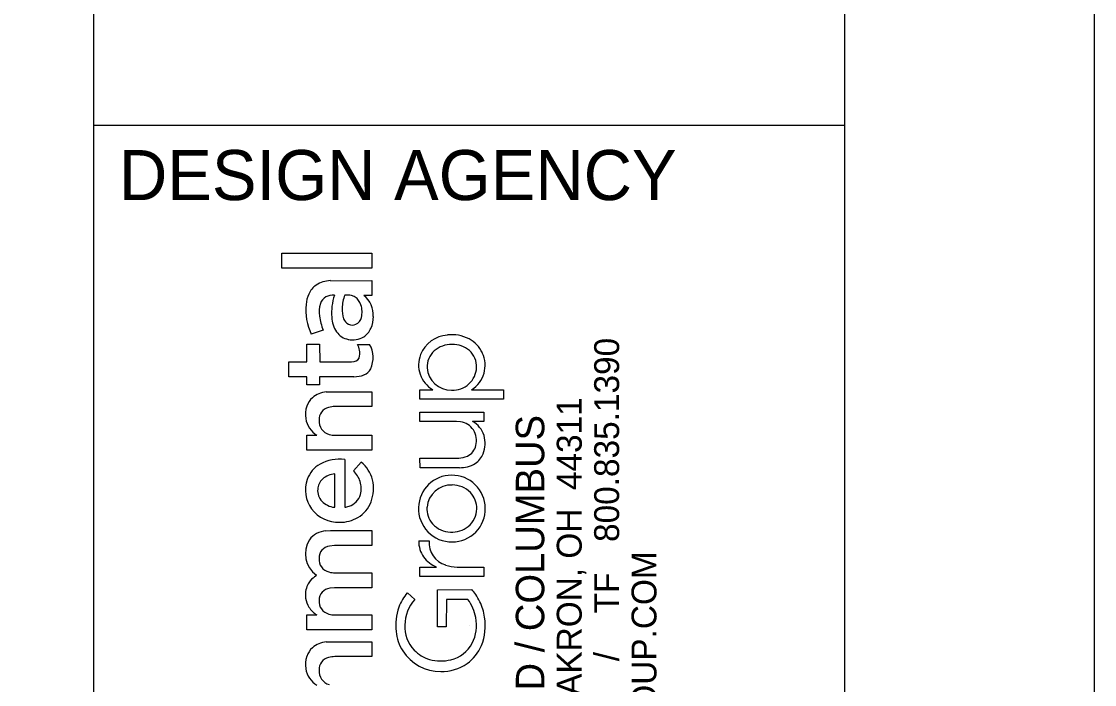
# Model space of a CAD drawing. Extents: x -0.3 to 34, y 0 to 22.
# Drawn here: x 31.855 to 34, y 3.382 to 4.707 of the extents above; entities that cross this region are included whole.
import ezdxf

# ---------------------------------------------------------------- set-up
doc = ezdxf.new("R2010")
doc.units = 0
for name, color, linetype in [('PM_X_CL_Pass_Proh_Lt', 7, 'Continuous'), ('PM_X_Edge_Line', 7, 'Continuous'), ('PM_X_Stop_Line', 7, 'Continuous')]:
    doc.layers.add(name, color=color, linetype=linetype)

msp = doc.modelspace()

# ---------------------------------------------------------------- linework, layer by layer
at = {"layer": 'PM_X_CL_Pass_Proh_Lt'}
msp.add_lwpolyline([(0, 0), (34, 0), (34, 22), (0, 22)], close=True, dxfattribs=at)
at = {"layer": 'PM_X_Edge_Line'}
for p, q in [((32.3756, 4.2141), (32.3756, 4.244)), ((32.3756, 4.244), (32.5557, 4.244)), ((32.5557, 4.244), (32.5557, 4.2141)), ((32.5557, 4.2141), (32.3756, 4.2141)), ((32.4727, 4.189), (32.5555, 4.1892)), ((32.5555, 4.1892), (32.5557, 4.1596)), ((32.5557, 4.1596), (32.5397, 4.1596)), ((32.4582, 4.0904), (32.4343, 4.0823)), ((32.4254, 4.027), (32.4255, 4.0621)), ((32.4255, 4.0621), (32.4511, 4.0621)), ((32.4511, 4.0621), (32.4512, 4.027)), ((32.527, 4.0616), (32.5511, 4.0616)), ((32.3896, 3.9972), (32.3896, 4.027)), ((32.3896, 4.027), (32.4254, 4.027)), ((32.4512, 4.027), (32.515, 4.027)), ((32.515, 4.027), (32.52, 4.0275)), ((32.4254, 3.9972), (32.3896, 3.9972)), ((32.4254, 3.9807), (32.4254, 3.9972)), ((32.5197, 3.9972), (32.4511, 3.9972)), ((32.4511, 3.9972), (32.4511, 3.9807)), ((32.4511, 3.9807), (32.4254, 3.9807)), ((32.6515, 3.9521), (32.6515, 3.9711)), ((32.6515, 3.9711), (32.6771, 3.9711)), ((32.7549, 3.9713), (32.8186, 3.9711)), ((32.8186, 3.9711), (32.8184, 3.9521)), ((32.4644, 3.9669), (32.4729, 3.9673)), ((32.4729, 3.9673), (32.5557, 3.9673)), ((32.5557, 3.9673), (32.5557, 3.9375)), ((32.8184, 3.9521), (32.6515, 3.9521)), ((32.5557, 3.9375), (32.4814, 3.9375)), ((32.6515, 3.908), (32.6515, 3.9267)), ((32.6515, 3.9267), (32.7791, 3.9266)), ((32.7791, 3.9266), (32.7791, 3.908)), ((32.7249, 3.908), (32.6515, 3.908)), ((32.7328, 3.9073), (32.7249, 3.908)), ((32.7791, 3.908), (32.7569, 3.908)), ((32.4254, 3.8503), (32.4254, 3.8802)), ((32.4254, 3.8802), (32.4455, 3.8802)), ((32.4822, 3.8802), (32.5557, 3.8802)), ((32.5557, 3.8802), (32.5557, 3.8504)), ((32.5557, 3.8504), (32.4254, 3.8503)), ((32.5011, 3.8321), (32.5012, 3.7366)), ((32.5188, 3.8093), (32.5342, 3.8266)), ((32.6515, 3.8344), (32.7291, 3.8345)), ((32.6517, 3.8154), (32.6515, 3.8344)), ((32.4814, 3.7364), (32.4814, 3.803)), ((32.7307, 3.8154), (32.6517, 3.8154)), ((32.4802, 3.7363), (32.4814, 3.7364)), ((32.4633, 3.6891), (32.4726, 3.6897)), ((32.4726, 3.6897), (32.5556, 3.6897)), ((32.5556, 3.6897), (32.5557, 3.6598)), ((32.6493, 3.6691), (32.6698, 3.6691)), ((32.4806, 3.6598), (32.471, 3.6588)), ((32.5557, 3.6598), (32.4806, 3.6598)), ((32.4822, 3.6055), (32.5557, 3.6055)), ((32.5557, 3.6055), (32.5557, 3.5757)), ((32.6515, 3.598), (32.6515, 3.617)), ((32.6515, 3.617), (32.6848, 3.617)), ((32.726, 3.617), (32.7791, 3.617)), ((32.7791, 3.617), (32.779, 3.598)), ((32.4444, 3.5992), (32.4446, 3.6007)), ((32.779, 3.598), (32.6515, 3.598)), ((32.4809, 3.5757), (32.4714, 3.5747)), ((32.5557, 3.5757), (32.4809, 3.5757)), ((32.6264, 3.5655), (32.6411, 3.5524)), ((32.6868, 3.5718), (32.7552, 3.5719)), ((32.6868, 3.4978), (32.6868, 3.5718)), ((32.7045, 3.5524), (32.7043, 3.4978)), ((32.7474, 3.5523), (32.7045, 3.5524)), ((32.4254, 3.4915), (32.4254, 3.5214)), ((32.4254, 3.5214), (32.4451, 3.5214)), ((32.4821, 3.5214), (32.5557, 3.5214)), ((32.5557, 3.5214), (32.5557, 3.4916)), ((32.7043, 3.4978), (32.6868, 3.4978)), ((32.75, 3.5), (32.75, 3.5)), ((32.5557, 3.4916), (32.4254, 3.4915)), ((32.4644, 3.4674), (32.4729, 3.4678)), ((32.4729, 3.4678), (32.5557, 3.4678)), ((32.5557, 3.4678), (32.5557, 3.438)), ((32.5557, 3.438), (32.4814, 3.438))]:
    msp.add_line(p, q, dxfattribs=at)
msp.add_lwpolyline([(32.3756, 4.2141), (32.3756, 4.244), (32.5557, 4.244), (32.5557, 4.2141)], close=True, dxfattribs=at)
for points in [[(32.4727, 4.189), (32.5555, 4.1892), (32.5557, 4.1596)], [(32.5557, 4.1596), (32.5397, 4.1596)], [(32.4582, 4.0904), (32.4343, 4.0823)], [(32.5197, 3.9972), (32.4511, 3.9972), (32.4511, 3.9807), (32.4254, 3.9807), (32.4254, 3.9972), (32.3896, 3.9972), (32.3896, 4.027), (32.4254, 4.027), (32.4255, 4.0621), (32.4511, 4.0621), (32.4512, 4.027), (32.515, 4.027), (32.52, 4.0275)], [(32.527, 4.0616), (32.5511, 4.0616)], [(32.7549, 3.9713), (32.8186, 3.9711), (32.8184, 3.9521), (32.6515, 3.9521)], [(32.6515, 3.9521), (32.6515, 3.9711), (32.6771, 3.9711)], [(32.4644, 3.9669), (32.4729, 3.9673), (32.5557, 3.9673), (32.5557, 3.9375), (32.4814, 3.9375)], [(32.7328, 3.9073), (32.7249, 3.908), (32.6515, 3.908), (32.6515, 3.9267), (32.7791, 3.9266), (32.7791, 3.908), (32.7569, 3.908)], [(32.4254, 3.8503), (32.4254, 3.8802), (32.4455, 3.8802)], [(32.4822, 3.8802), (32.5557, 3.8802), (32.5557, 3.8504), (32.4254, 3.8503)], [(32.5011, 3.8321), (32.5012, 3.7366)], [(32.5188, 3.8093), (32.5342, 3.8266)], [(32.7307, 3.8154), (32.6517, 3.8154), (32.6515, 3.8344), (32.7291, 3.8345)], [(32.4802, 3.7363), (32.4814, 3.7364), (32.4814, 3.803)], [(32.4633, 3.6891), (32.4726, 3.6897), (32.5556, 3.6897), (32.5557, 3.6598), (32.4806, 3.6598), (32.471, 3.6588)], [(32.6493, 3.6691), (32.6698, 3.6691)], [(32.4822, 3.6055), (32.5557, 3.6055), (32.5557, 3.5757), (32.4809, 3.5757), (32.4714, 3.5747)], [(32.6515, 3.598), (32.6515, 3.617), (32.6848, 3.617)], [(32.726, 3.617), (32.7791, 3.617), (32.779, 3.598), (32.6515, 3.598)], [(32.4444, 3.5992), (32.4446, 3.6007)], [(32.6264, 3.5655), (32.6411, 3.5524)], [(32.7474, 3.5523), (32.7045, 3.5524), (32.7043, 3.4978), (32.6868, 3.4978), (32.6868, 3.5718), (32.7552, 3.5719)], [(32.4254, 3.4915), (32.4254, 3.5214), (32.4451, 3.5214)], [(32.4821, 3.5214), (32.5557, 3.5214), (32.5557, 3.4916), (32.4254, 3.4915)], [(32.4644, 3.4674), (32.4729, 3.4678), (32.5557, 3.4678), (32.5557, 3.438), (32.4814, 3.438)]]:
    msp.add_lwpolyline(points, dxfattribs=at)
for centre, radius, start, end in [((32.4745, 4.1326), 0.0565, 91.8942, 122.6317), ((32.4745, 4.1326), 0.0565, 91.8942, 122.6317), ((32.4882, 4.1361), 0.0646, 155.9764, 175.3149), ((32.4882, 4.1361), 0.0646, 155.9764, 175.3149), ((32.4685, 4.1447), 0.043, 124.537, 155.6594), ((32.4685, 4.1447), 0.043, 124.537, 155.6594), ((32.5364, 4.1308), 0.113, 174.6101, 205.3899), ((32.5364, 4.1308), 0.113, 174.6101, 205.3899), ((32.5076, 4.1265), 0.0576, 163.1369, 188.1675), ((32.5076, 4.1265), 0.0576, 163.1369, 188.1675), ((32.4753, 4.1356), 0.024, 119.4252, 161.6629), ((32.4753, 4.1356), 0.024, 119.4252, 161.6629), ((32.4779, 4.1278), 0.0321, 85.3802, 116.6222), ((32.4779, 4.1278), 0.0321, 85.3802, 116.6222), ((32.5879, 4.1251), 0.1129, 162.0821, 184.5285), ((32.5879, 4.1251), 0.1129, 162.0821, 184.5285), ((32.5801, 4.1313), 0.0841, 159.8366, 178.0362), ((32.5801, 4.1313), 0.0841, 159.8366, 178.0362), ((32.5051, 4.1074), 0.053, 79.6696, 94.2322), ((32.5051, 4.1074), 0.053, 79.6696, 94.2322), ((32.5089, 4.1364), 0.0238, 56.8913, 76.2149), ((32.5089, 4.1364), 0.0238, 56.8913, 76.2149), ((32.5052, 4.1318), 0.0297, 17.5984, 55.7282), ((32.5052, 4.1318), 0.0297, 17.5984, 55.7282), ((32.4916, 4.1264), 0.0443, 345.9408, 18.9919), ((32.4916, 4.1264), 0.0443, 345.9408, 18.9919), ((32.5055, 4.1191), 0.0529, 358.0746, 49.762), ((32.5055, 4.1191), 0.0529, 358.0746, 49.762), ((32.5466, 4.1303), 0.0506, 175.5903, 199.8857), ((32.5466, 4.1303), 0.0506, 175.5903, 199.8857), ((32.5473, 4.1297), 0.0973, 186.7598, 203.7981), ((32.5473, 4.1297), 0.0973, 186.7598, 203.7981), ((32.5328, 4.1187), 0.0575, 182.5676, 213.7144), ((32.5328, 4.1187), 0.0575, 182.5676, 213.7144), ((32.5164, 4.1189), 0.0184, 198.2844, 293.3081), ((32.5164, 4.1189), 0.0184, 198.2844, 293.3081), ((32.5152, 4.1199), 0.0199, 295.2883, 347.4639), ((32.5152, 4.1199), 0.0199, 295.2883, 347.4639), ((32.5019, 4.1168), 0.0566, 336.016, 0.5951), ((32.5019, 4.1168), 0.0566, 336.016, 0.5951), ((32.5149, 4.1078), 0.0366, 215.0668, 259.8133), ((32.5149, 4.1078), 0.0366, 215.0668, 259.8133), ((32.5175, 4.1131), 0.0423, 257.5256, 300.882), ((32.5175, 4.1131), 0.0423, 257.5256, 300.882), ((32.5175, 4.1097), 0.0394, 303.4436, 336.18), ((32.5175, 4.1097), 0.0394, 303.4436, 336.18), ((32.7108, 4.0182), 0.0624, 93.9866, 158.3119), ((32.7108, 4.0182), 0.0624, 93.9866, 158.3119), ((32.7156, 4.0065), 0.0746, 62.6889, 97.0135), ((32.7156, 4.0065), 0.0746, 62.6889, 97.0135), ((32.4863, 4.042), 0.0452, 10.1545, 25.723), ((32.4863, 4.042), 0.0452, 10.1545, 25.723), ((32.503, 4.0351), 0.0549, 336.589, 28.8991), ((32.503, 4.0351), 0.0549, 336.589, 28.8991), ((32.7138, 4.0102), 0.0513, 87.8965, 131.1812), ((32.7138, 4.0102), 0.0513, 87.8965, 131.1812), ((32.7175, 4.0102), 0.0513, 49.9089, 92.0363), ((32.7175, 4.0102), 0.0513, 49.9089, 92.0363), ((32.7212, 4.0191), 0.0608, 25.0657, 61.9602), ((32.7212, 4.0191), 0.0608, 25.0657, 61.9602), ((32.5184, 4.04), 0.0126, 277.6142, 353.7918), ((32.5184, 4.04), 0.0126, 277.6142, 353.7918), ((32.4957, 4.0436), 0.0356, 351.914, 10.2059), ((32.4957, 4.0436), 0.0356, 351.914, 10.2059), ((32.707, 4.0202), 0.0581, 158.656, 198.171), ((32.707, 4.0202), 0.0581, 158.656, 198.171), ((32.7092, 4.0167), 0.0434, 132.3289, 182.0949), ((32.7092, 4.0167), 0.0434, 132.3289, 182.0949), ((32.7215, 4.0173), 0.0433, 358.0487, 47.9447), ((32.7215, 4.0173), 0.0433, 358.0487, 47.9447), ((32.7245, 4.02), 0.0574, 301.9776, 25.6418), ((32.7245, 4.02), 0.0574, 301.9776, 25.6418), ((32.5291, 4.0261), 0.0275, 292.6889, 332.0598), ((32.5291, 4.0261), 0.0275, 292.6889, 332.0598), ((32.7135, 4.0181), 0.0478, 183.5974, 271.7045), ((32.7135, 4.0181), 0.0478, 183.5974, 271.7045), ((32.7172, 4.018), 0.0477, 267.3149, 357.4019), ((32.7172, 4.018), 0.0477, 267.3149, 357.4019), ((32.5209, 4.0486), 0.0514, 268.6727, 291.5235), ((32.5209, 4.0486), 0.0514, 268.6727, 291.5235), ((32.7103, 4.0243), 0.0627, 200.8399, 238.0162), ((32.7103, 4.0243), 0.0627, 200.8399, 238.0162), ((32.4635, 3.9255), 0.0402, 132.2238, 161.6823), ((32.4635, 3.9255), 0.0402, 132.2238, 161.6823), ((32.4687, 3.9172), 0.0499, 94.9706, 130.2248), ((32.4687, 3.9172), 0.0499, 94.9706, 130.2248), ((32.4787, 3.9211), 0.056, 162.274, 187.7917), ((32.4787, 3.9211), 0.056, 162.274, 187.7917), ((32.4748, 3.9116), 0.025, 103.6868, 182.214), ((32.4748, 3.9116), 0.025, 103.6868, 182.214), ((32.4811, 3.8915), 0.046, 89.6051, 105.3303), ((32.4811, 3.8915), 0.046, 89.6051, 105.3303), ((32.4703, 3.9209), 0.0476, 188.9646, 238.6987), ((32.4703, 3.9209), 0.0476, 188.9646, 238.6987), ((32.4774, 3.9085), 0.0276, 175.5844, 255.1382), ((32.4774, 3.9085), 0.0276, 175.5844, 255.1382), ((32.7271, 3.87), 0.0377, 33.5008, 81.3295), ((32.7271, 3.87), 0.0377, 33.5008, 81.3295), ((32.7324, 3.8648), 0.0496, 17.6221, 60.3897), ((32.7324, 3.8648), 0.0496, 17.6221, 60.3897), ((32.7241, 3.8695), 0.0405, 346.5618, 31.7539), ((32.7241, 3.8695), 0.0405, 346.5618, 31.7539), ((32.4818, 3.9224), 0.0421, 254.0891, 270.5284), ((32.4818, 3.9224), 0.0421, 254.0891, 270.5284), ((32.7234, 3.8641), 0.0584, 339.162, 15.6148), ((32.7234, 3.8641), 0.0584, 339.162, 15.6148), ((32.7337, 3.8662), 0.0304, 294.6321, 348.4863), ((32.7337, 3.8662), 0.0304, 294.6321, 348.4863), ((32.739, 3.859), 0.042, 303.1039, 338.1561), ((32.739, 3.859), 0.042, 303.1039, 338.1561), ((32.4789, 3.7737), 0.0558, 118.8294, 160.6224), ((32.4789, 3.7737), 0.0558, 118.8294, 160.6224), ((32.4918, 3.7487), 0.0839, 83.6212, 118.2845), ((32.4918, 3.7487), 0.0839, 83.6212, 118.2845), ((32.494, 3.7763), 0.0644, 13.5328, 51.3627), ((32.494, 3.7763), 0.0644, 13.5328, 51.3627), ((32.7275, 3.8808), 0.0463, 271.952, 294.0894), ((32.7275, 3.8808), 0.0463, 271.952, 294.0894), ((32.7321, 3.8726), 0.0571, 268.627, 301.4778), ((32.7321, 3.8726), 0.0571, 268.627, 301.4778), ((32.4844, 3.7607), 0.0424, 94.0131, 130.8806), ((32.4844, 3.7607), 0.0424, 94.0131, 130.8806), ((32.4803, 3.7702), 0.0549, 19.0387, 45.4432), ((32.4803, 3.7702), 0.0549, 19.0387, 45.4432), ((32.7143, 3.7348), 0.0655, 89.4821, 178.7775), ((32.7143, 3.7348), 0.0655, 89.4821, 178.7775), ((32.7158, 3.7341), 0.0662, 0.4227, 90.7613), ((32.7158, 3.7341), 0.0662, 0.4227, 90.7613), ((32.487, 3.7707), 0.0644, 160.5214, 215.7815), ((32.487, 3.7707), 0.0644, 160.5214, 215.7815), ((32.477, 3.7709), 0.0298, 132.9855, 177.1802), ((32.477, 3.7709), 0.0298, 132.9855, 177.1802), ((32.4872, 3.7743), 0.047, 344.6072, 17.0067), ((32.4872, 3.7743), 0.047, 344.6072, 17.0067), ((32.4829, 3.7738), 0.0758, 339.3543, 13.3771), ((32.4829, 3.7738), 0.0758, 339.3543, 13.3771), ((32.714, 3.7324), 0.0485, 87.6883, 175.017), ((32.714, 3.7324), 0.0485, 87.6883, 175.017), ((32.7166, 3.7304), 0.0505, 44.912, 90.7591), ((32.7166, 3.7304), 0.0505, 44.912, 90.7591), ((32.4782, 3.7697), 0.0311, 175.0014, 223.2876), ((32.4782, 3.7697), 0.0311, 175.0014, 223.2876), ((32.499, 3.7718), 0.035, 288.0108, 343.5536), ((32.499, 3.7718), 0.035, 288.0108, 343.5536), ((32.7196, 3.7345), 0.0455, 358.3228, 43.8349), ((32.7196, 3.7345), 0.0455, 358.3228, 43.8349), ((32.4891, 3.7752), 0.0687, 217.7434, 271.6561), ((32.4891, 3.7752), 0.0687, 217.7434, 271.6561), ((32.4855, 3.7783), 0.0423, 225.0645, 262.797), ((32.4855, 3.7783), 0.0423, 225.0645, 262.797), ((32.5013, 3.7568), 0.0202, 269.7004, 294.8729), ((32.5013, 3.7568), 0.0202, 269.7004, 294.8729), ((32.4955, 3.7698), 0.0626, 300.9439, 338.7322), ((32.4955, 3.7698), 0.0626, 300.9439, 338.7322), ((32.7148, 3.7334), 0.0661, 177.5373, 270.9452), ((32.7148, 3.7334), 0.0661, 177.5373, 270.9452), ((32.7108, 3.7331), 0.0453, 175.5147, 221.4205), ((32.7108, 3.7331), 0.0453, 175.5147, 221.4205), ((32.7167, 3.7327), 0.0654, 269.3083, 1.6791), ((32.7167, 3.7327), 0.0654, 269.3083, 1.6791), ((32.7193, 3.7337), 0.0457, 308.9038, 359.3095), ((32.7193, 3.7337), 0.0457, 308.9038, 359.3095), ((32.492, 3.777), 0.0706, 269.2053, 300.3357), ((32.492, 3.777), 0.0706, 269.2053, 300.3357), ((32.714, 3.7373), 0.0505, 222.6626, 268.3733), ((32.714, 3.7373), 0.0505, 222.6626, 268.3733), ((32.7157, 3.7386), 0.0518, 266.5531, 308.6725), ((32.7157, 3.7386), 0.0518, 266.5531, 308.6725), ((32.4759, 3.6437), 0.0532, 148.2879, 233.9556), ((32.4759, 3.6437), 0.0532, 148.2879, 233.9556), ((32.4664, 3.644), 0.0452, 93.9112, 142.3072), ((32.4664, 3.644), 0.0452, 93.9112, 142.3072), ((32.6988, 3.6666), 0.0495, 177.1621, 216.2802), ((32.6988, 3.6666), 0.0495, 177.1621, 216.2802), ((32.7173, 3.6664), 0.0476, 176.7699, 252.1504), ((32.7173, 3.6664), 0.0476, 176.7699, 252.1504), ((32.4738, 3.635), 0.024, 96.7576, 181.6251), ((32.4738, 3.635), 0.024, 96.7576, 181.6251), ((32.4758, 3.6324), 0.026, 175.8157, 256.1672), ((32.4758, 3.6324), 0.026, 175.8157, 256.1672), ((32.7098, 3.6755), 0.0637, 216.9153, 246.8862), ((32.7098, 3.6755), 0.0637, 216.9153, 246.8862), ((32.4817, 3.6505), 0.045, 254.3463, 270.6103), ((32.4817, 3.6505), 0.045, 254.3463, 270.6103), ((32.7269, 3.6917), 0.0747, 251.1388, 269.3469), ((32.7269, 3.6917), 0.0747, 251.1388, 269.3469), ((32.4619, 3.5645), 0.0387, 139.5245, 154.847), ((32.4619, 3.5645), 0.0387, 139.5245, 154.847), ((32.4638, 3.5627), 0.0414, 117.9163, 139.243), ((32.4638, 3.5627), 0.0414, 117.9163, 139.243), ((32.4714, 3.5612), 0.0488, 156.0638, 187.3493), ((32.4714, 3.5612), 0.0488, 156.0638, 187.3493), ((32.4742, 3.5506), 0.0243, 96.5532, 179.949), ((32.4742, 3.5506), 0.0243, 96.5532, 179.949), ((32.7016, 3.5019), 0.0986, 139.7948, 159.137), ((32.7016, 3.5019), 0.0986, 139.7948, 159.137), ((32.725, 3.5394), 0.0444, 30.9891, 47.161), ((32.725, 3.5394), 0.0444, 30.9891, 47.161), ((32.6709, 3.5002), 0.1111, 25.3031, 33.9618), ((32.6709, 3.5002), 0.1111, 25.3031, 33.9618), ((32.4646, 3.5597), 0.0418, 186.5579, 213.3885), ((32.4646, 3.5597), 0.0418, 186.5579, 213.3885), ((32.4761, 3.5486), 0.0263, 175.722, 255.7863), ((32.4761, 3.5486), 0.0263, 175.722, 255.7863), ((32.699, 3.5008), 0.0775, 138.258, 179.7006), ((32.699, 3.5008), 0.0775, 138.258, 179.7006), ((32.6789, 3.501), 0.0856, 10.0751, 36.8319), ((32.6789, 3.501), 0.0856, 10.0751, 36.8319), ((32.6704, 3.4999), 0.1117, 8.8034, 25.3348), ((32.6704, 3.4999), 0.1117, 8.8034, 25.3348), ((32.4789, 3.5708), 0.0598, 214.7043, 235.6872), ((32.4789, 3.5708), 0.0598, 214.7043, 235.6872), ((32.4819, 3.5652), 0.0438, 253.6672, 270.1498), ((32.4819, 3.5652), 0.0438, 253.6672, 270.1498), ((32.7187, 3.4997), 0.1154, 161.1438, 185.6281), ((32.7187, 3.4997), 0.1154, 161.1438, 185.6281), ((32.6881, 3.4973), 0.0668, 176.6658, 223.6912), ((32.6881, 3.4973), 0.0668, 176.6658, 223.6912), ((32.6842, 3.5006), 0.0804, 333.4669, 11.0367), ((32.6842, 3.5006), 0.0804, 333.4669, 11.0367), ((32.6756, 3.4998), 0.1065, 338.2887, 9.2855), ((32.6756, 3.4998), 0.1065, 338.2887, 9.2855), ((32.6934, 3.497), 0.0899, 185.5077, 212.0129), ((32.6934, 3.497), 0.0899, 185.5077, 212.0129), ((32.4635, 3.426), 0.0402, 132.2238, 161.6823), ((32.4635, 3.426), 0.0402, 132.2238, 161.6823), ((32.4687, 3.4177), 0.0499, 94.9706, 130.2248), ((32.4687, 3.4177), 0.0499, 94.9706, 130.2248), ((32.6987, 3.4955), 0.0652, 282.8815, 331.8147), ((32.6987, 3.4955), 0.0652, 282.8815, 331.8147), ((32.6984, 3.4917), 0.0824, 305.0306, 337.6757), ((32.6984, 3.4917), 0.0824, 305.0306, 337.6757), ((32.4787, 3.4216), 0.056, 162.274, 187.7917), ((32.4787, 3.4216), 0.056, 162.274, 187.7917), ((32.4748, 3.4121), 0.025, 103.6868, 182.214), ((32.4748, 3.4121), 0.025, 103.6868, 182.214), ((32.4811, 3.392), 0.046, 89.6051, 105.3303), ((32.4811, 3.392), 0.046, 89.6051, 105.3303), ((32.6921, 3.4975), 0.0891, 212.7022, 270.714), ((32.6921, 3.4975), 0.0891, 212.7022, 270.714), ((32.6905, 3.5001), 0.0704, 224.0215, 253.88), ((32.6905, 3.5001), 0.0704, 224.0215, 253.88), ((32.6932, 3.5125), 0.0831, 254.4535, 283.9512), ((32.6932, 3.5125), 0.0831, 254.4535, 283.9512), ((32.4703, 3.4214), 0.0476, 188.9646, 238.6987), ((32.4703, 3.4214), 0.0476, 188.9646, 238.6987), ((32.4774, 3.409), 0.0276, 175.5844, 255.1382), ((32.4774, 3.409), 0.0276, 175.5844, 255.1382), ((32.6943, 3.4998), 0.0914, 269.3273, 304.1963), ((32.6943, 3.4998), 0.0914, 269.3273, 304.1963)]:
    msp.add_arc(centre, radius, start, end, dxfattribs=at)
at = {"layer": 'PM_X_Stop_Line'}
for p, q in [((32, 0.5), (32, 21.5)), ((32, 4.5), (33.5, 4.5))]:
    msp.add_line(p, q, dxfattribs=at)
msp.add_lwpolyline([(1.5, 21.5), (33.5, 21.5), (33.5, 0.5), (1.5, 0.5)], close=True, dxfattribs=at)

# ---------------------------------------------------------------- texts
at = {"layer": 'PM_X_Edge_Line'}
msp.add_text('DESIGN AGENCY', height=0.1, dxfattribs=at).set_placement((32.05, 4.35))
for s, height, p in [('800.835.1390', 0.049846, (33.0497, 3.6671)), ('450 GRANT ST., AKRON, OH  44311', 0.049846, (32.9749, 2.8374)), ('AKRON / CLEVELAND / COLUMBUS', 0.056969, (32.9001, 2.638)), ('ENVDESIGNGROUP.COM', 0.049846, (33.1244, 2.8374)), ('TF', 0.04985, (33.0497, 3.5246)), ('/  ', 0.04985, (33.0497, 3.4288))]:
    msp.add_text(s, height=height, rotation=90, dxfattribs=at).set_placement(p)

doc.saveas('drawing.dxf')
